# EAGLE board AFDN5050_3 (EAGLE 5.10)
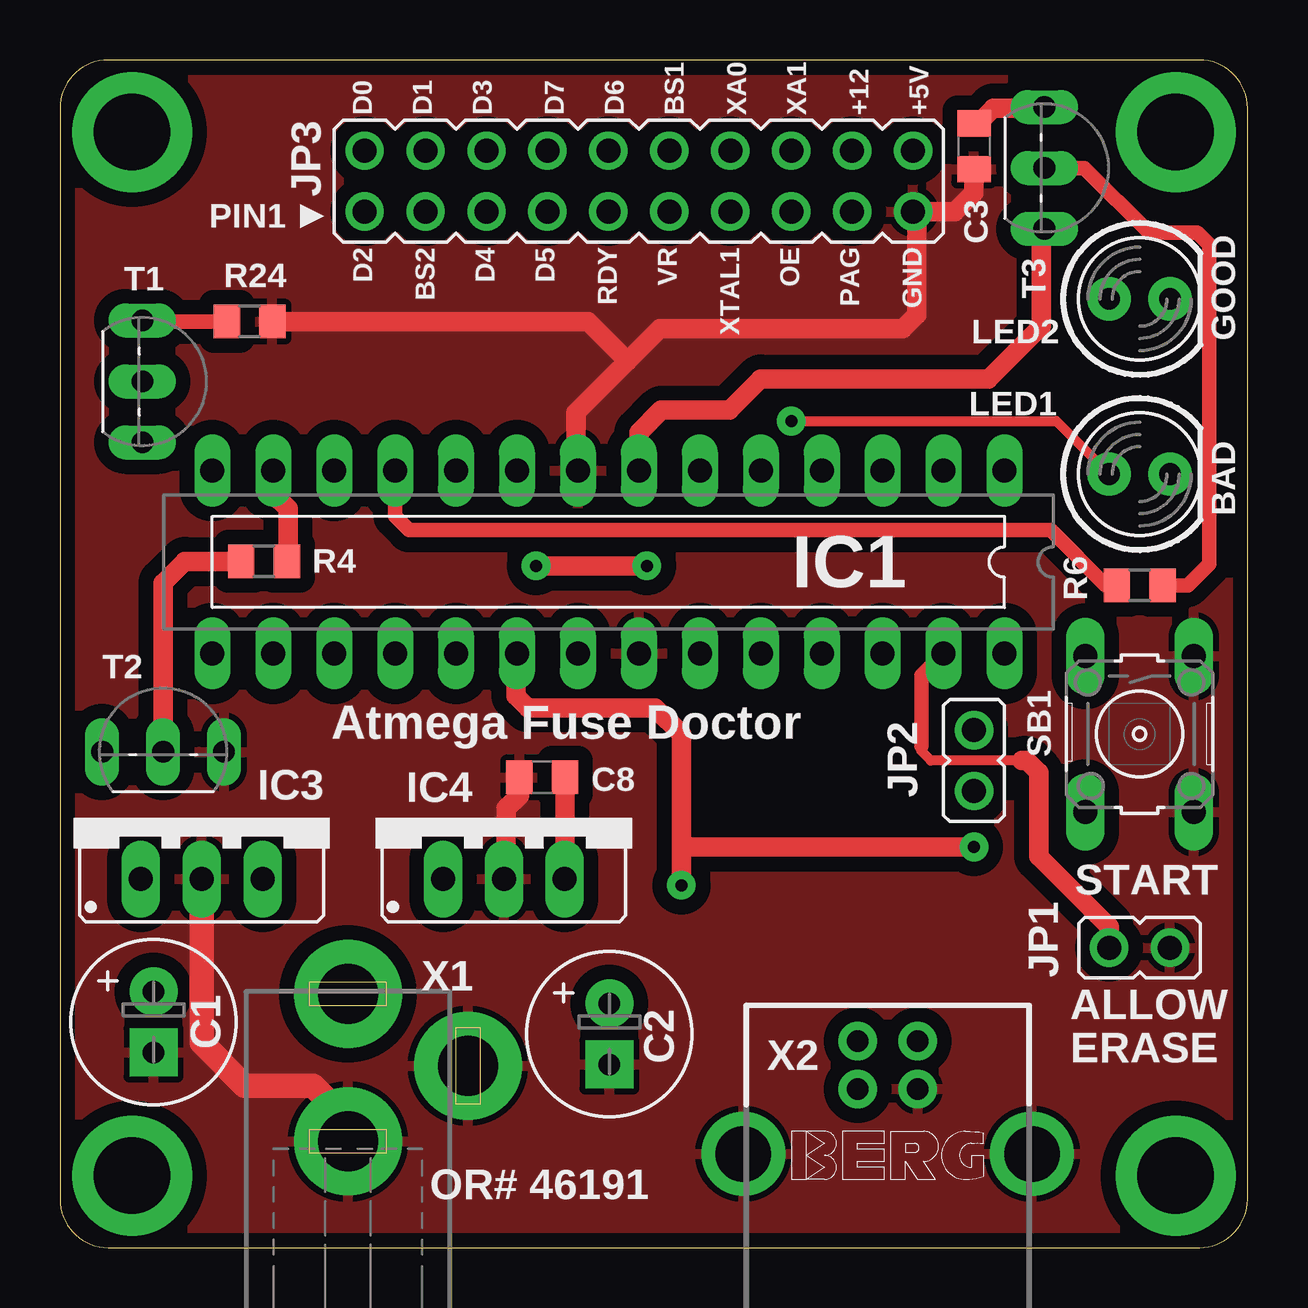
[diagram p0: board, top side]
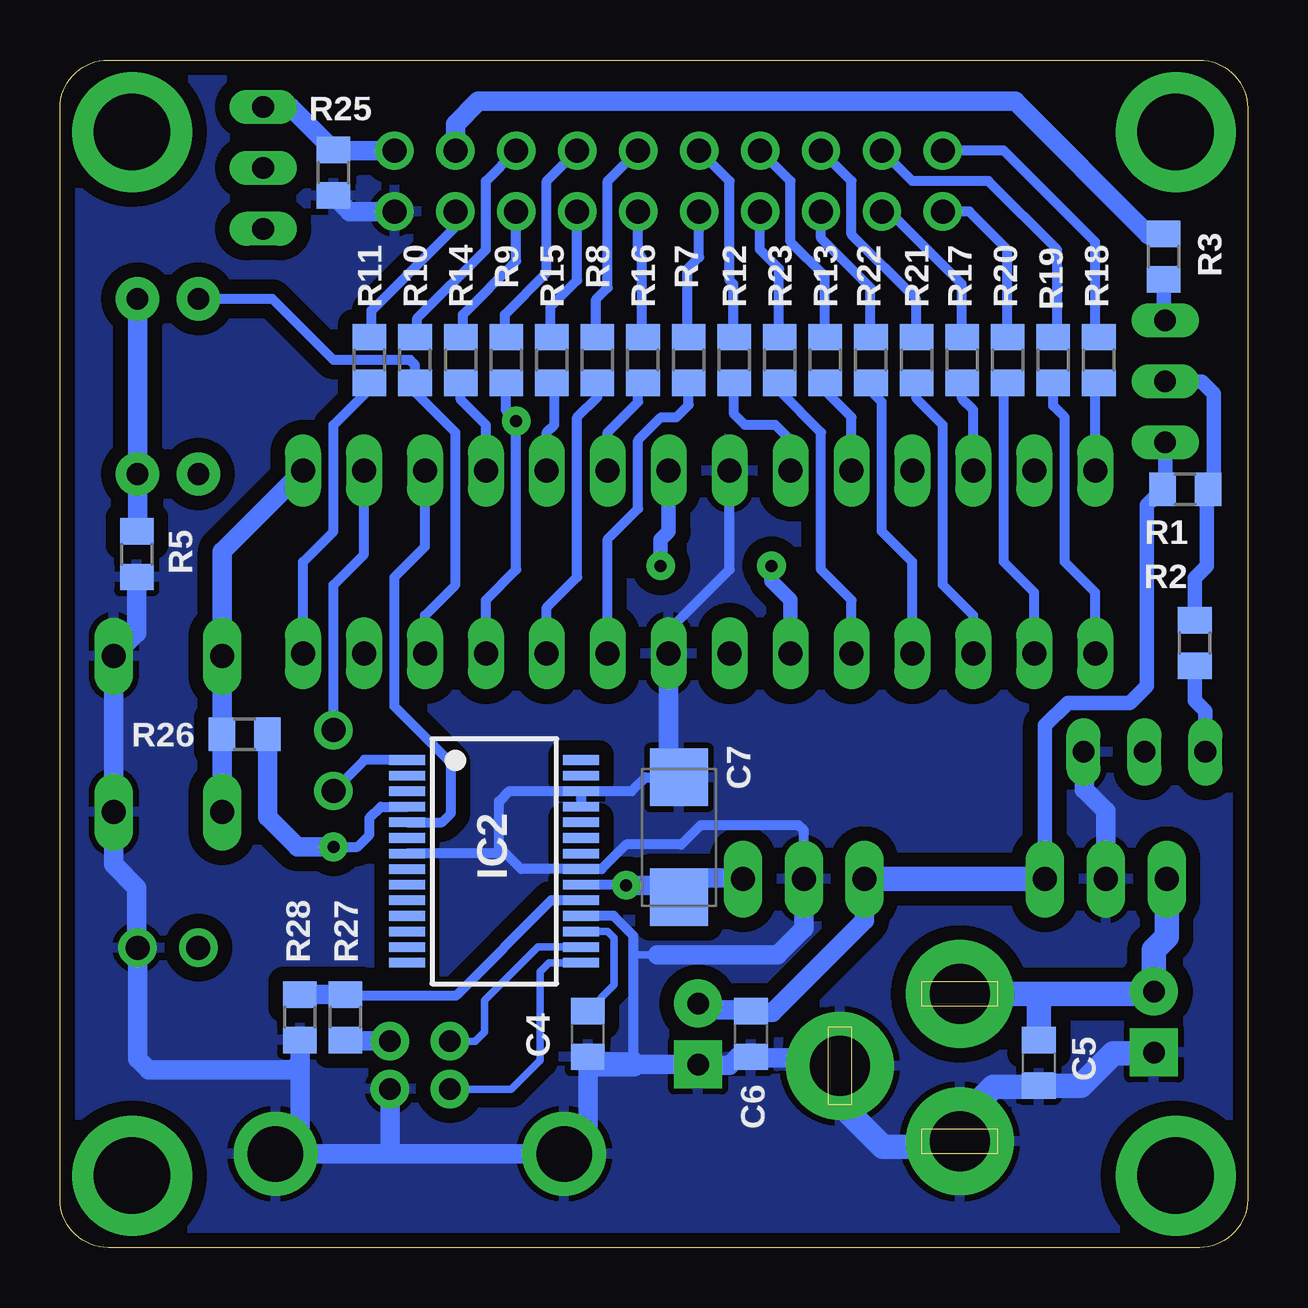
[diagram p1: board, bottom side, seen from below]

Size 49.5 x 49.5 mm. Coordinates in mm from the lower left corner, seen from the top.
Outline: 49.5,47.5 arc90 47.5,49.5 2,49.5 arc90 0,47.5 0,2 arc90 2,0 47.5,0 arc90 49.5,2 49.5,47.5
Copper layers (1*16): Top 0.035mm / dielectric 1.5mm / Bottom 0.035mm
Design rules "Fusion_eagle_rule_v1.1": minimum track width 6mil, minimum drill 12mil, track to track 6mil, track to pad 6mil, pad to pad 6mil, via to via 6mil, smd to smd 0mil, copper to edge 10mil, drill to drill 10mil, minimum pad ring 10mil, minimum via ring 6mil, stop-mask expansion 2mil, vias tented up to drill 100mil, thermal gap 10mil

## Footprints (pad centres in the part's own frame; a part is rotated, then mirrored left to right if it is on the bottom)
E2,5-7 = drill 0.9 pad 2 round: + -1.27,0 | drill 0.9 pad 2 square: - 1.27,0
C0805 = smd 1.1 x 1.4: 1 -0.95,0; 2 0.95,0
SMC_C = smd 2.4 x 2.4: + -2.5,0; - 2.5,0
DIL28-3 = drill 1 pad 1.3 long: 1 -16.51,-3.81; 2 -13.97,-3.81; 3 -11.43,-3.81; 4 -8.89,-3.81; 5 -6.35,-3.81; 6 -3.81,-3.81; 7 -1.27,-3.81; 8 1.27,-3.81; 9 3.81,-3.81; 10 6.35,-3.81; 11 8.89,-3.81; 12 11.43,-3.81; 13 13.97,-3.81; 14 16.51,-3.81; 15 16.51,3.81; 16 13.97,3.81; 17 11.43,3.81; 18 8.89,3.81; 19 6.35,3.81; 20 3.81,3.81; 21 1.27,3.81; 22 -1.27,3.81; 23 -3.81,3.81; 24 -6.35,3.81; 25 -8.89,3.81; 26 -11.43,3.81; 27 -13.97,3.81; 28 -16.51,3.81
SSOP28 = smd 0.4 x 1.5: 1 -4.225,-3.625; 2 -3.575,-3.625; 3 -2.925,-3.625; 4 -2.275,-3.625; 5 -1.625,-3.625; 6 -0.975,-3.625; 7 -0.325,-3.625; 8 0.325,-3.625; 9 0.975,-3.625; 10 1.625,-3.625; 11 2.275,-3.625; 12 2.925,-3.625; 13 3.575,-3.625; 14 4.225,-3.625; 15 4.225,3.625; 16 3.575,3.625; 17 2.925,3.625; 18 2.275,3.625; 19 1.625,3.625; 20 0.975,3.625; 21 0.325,3.625; 22 -0.325,3.625; 23 -0.975,3.625; 24 -1.625,3.625; 25 -2.275,3.625; 26 -2.925,3.625; 27 -3.575,3.625; 28 -4.225,3.625
78XXS = drill 1 pad 1.6 long: GND 0,-2.54; IN -2.54,-2.54; OUT 2.54,-2.54
JP1 = drill 1 pad 1.6 round: 1 0,-1.27; 2 0,1.27
JP10Q = drill 1 pad 1.6 round: 1 -11.43,-1.27; 2 -11.43,1.27; 3 -8.89,-1.27; 4 -8.89,1.27; 5 -6.35,-1.27; 6 -6.35,1.27; 7 -3.81,-1.27; 8 -3.81,1.27; 9 -1.27,-1.27; 10 -1.27,1.27; 11 1.27,-1.27; 12 1.27,1.27; 13 3.81,-1.27; 14 3.81,1.27; 15 6.35,-1.27; 16 6.35,1.27; 17 8.89,-1.27; 18 8.89,1.27; 19 11.43,-1.27; 20 11.43,1.27
LED5MM = drill 0.9 pad 1.8 round: A -1.27,0; K 1.27,0
R0805 = smd 1.1 x 1.4: 1 -0.95,0; 2 0.95,0
B3F-10XX = drill 1 pad 1.6 long: 1 -3.251,2.261; 2 3.251,2.261; 3 -3.251,-2.261; 4 3.251,-2.261
TO92-EBC = drill 0.9 pad 1.3 long: B 0,-1.27; C -2.54,-1.27; E 2.54,-1.27
733980-62 = drill 2.5 pad 4.5 round: 1 0,8.57; 2 0,2.42; 3 5,5.57
PN61729-S = drill 0.9 pad 1.6 round: 1 1.25,4.71; 2 -1.25,4.71; 3 -1.25,2.71; 4 1.25,2.71 | drill 2.3 pad 3.5 round: S1 -6.02,0; S2 6.02,0

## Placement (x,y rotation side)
C1  100m  [E2,5-7]  3.9,9.4 270 top
C2  10m  [E2,5-7]  22.9,8.9 270 top
C3  10n  [C0805]  38.1,45.9 270 top
C4  100n  [C0805]  27.5,8.9 90 bottom
C5  100n  [C0805]  8.7,7.7 270 bottom
C6  100n  [C0805]  20.7,8.9 270 bottom
C7  10m  [SMC_C]  23.7,17.1 90 bottom
C8  100n  [C0805]  20.1,19.6 180 top
IC1  MEGA8-P  [DIL28-3]  22.86,28.57 180 top
IC2  FT232RL  [SSOP28]  31.4,16.1 270 bottom
IC3  7812  [78XXS]  5.9,17.9 0 top
IC4  7805  [78XXS]  18.5,17.9 0 top
JP1  ERASE  [JP1]  45,12.5 90 top
JP2  TXD  [JP1]  38.1,20.3 0 top
JP3  PROG  [JP10Q]  24.13,44.45 0 top
LED1  RED  [LED5MM]  45,32.24 0 top
LED2  GREEN  [LED5MM]  45,39.54 0 top
R1  10K  [R0805]  2.6,31.6 180 bottom
R2  1K  [R0805]  2.2,25.2 90 bottom
R3  100E  [R0805]  3.5,41.3 90 bottom
R4  4K7  [R0805]  8.5,28.6 180 top
R5  330E  [R0805]  46.3,28.9 90 bottom
R6  4K7  [R0805]  45,27.6 0 top
R7  1K  [R0805]  23.3,37 90 bottom
R8  1K  [R0805]  27.1,37 90 bottom
R9  1K  [R0805]  30.9,37 90 bottom
R10  1K  [R0805]  34.7,37 90 bottom
R11  1K  [R0805]  36.6,37 90 bottom
R12  1K  [R0805]  21.4,37 90 bottom
R13  1K  [R0805]  17.6,37 90 bottom
R14  1K  [R0805]  32.8,37 90 bottom
R15  1K  [R0805]  29,37 90 bottom
R16  1K  [R0805]  25.2,37 90 bottom
R17  1K  [R0805]  11.9,37 90 bottom
R18  1K  [R0805]  6.2,37 90 bottom
R19  1K  [R0805]  8.1,37 90 bottom
R20  1K  [R0805]  10,37 90 bottom
R21  1K  [R0805]  13.8,37 90 bottom
R22  1K  [R0805]  15.7,37 90 bottom
R23  1K  [R0805]  19.5,37 90 bottom
R24  1K  [R0805]  7.9,38.6 180 top
R25  100E  [R0805]  38.1,44.8 90 bottom
R26  1K  [R0805]  41.8,21.4 0 bottom
R27  4K7  [R0805]  37.6,9.6 270 bottom
R28  10K  [R0805]  39.5,9.6 90 bottom
SB1  START  [B3F-10XX]  45,21.4 270 top
T1  BC557  [TO92-EBC]  4.7,36.1 270 top
T2  BC547  [TO92-EBC]  4.3,21.93 0 top
T3  BC557  [TO92-EBC]  42.3,45 270 top
X1  +12-15v  [733980-62]  12,2 0 top
X2  PN61729-S  [PN61729-S]  34.5,3.9 0 top

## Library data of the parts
C1 C2 IC1 IC3 IC4 JP1-JP3 LED1 LED2 SB1 T1-T3 X1 X2 = AFDN
C3-C8 R1-R28 = rcl
IC2 = ftdichip

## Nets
+5V: C3.1 JP3.20 R25.2 T3.C
+12V: JP3.18 R3.2
BS1: JP3.12 R8.2
BS2: JP3.3 R17.2
DATA0: JP3.2 R18.2
DATA1: JP3.4 R19.2
DATA2: JP3.1 R20.2
DATA3: JP3.6 R21.2
DATA4: JP3.5 R22.2
DATA5: JP3.7 R23.2
DATA6: JP3.10 R12.2
DATA7: JP3.8 R13.2
GND: C1.- C2.- C3.2 C4.1 C5.2 C6.2 C7.- C8.2 IC1.8 IC1.22 IC2.7 IC2.18 IC2.21 IC2.25 IC2.26 IC3.GND IC4.GND JP1.1 JP3.19 R5.1 R24.1 R25.1 R28.1 SB1.1 SB1.2 T2.E X1.2 X1.3 X2.4 X2.S1 X2.S2
N$1: IC1.1 R26.1 SB1.3 SB1.4
N$2: IC1.28 R11.1
N$3: IC1.2 JP2.2
N$4: IC2.1 JP2.1
N$5: IC1.26 LED2.A R10.1
N$6: IC1.25 LED1.A R9.1
N$7: IC1.24 R8.1
N$8: IC1.23 R7.1
N$9: IC1.4 R14.1
N$10: IC1.5 R15.1
N$11: IC1.6 R16.1
N$12: IC1.12 R17.1
N$13: IC1.14 R18.1
N$14: IC1.15 R19.1
N$15: IC1.16 R20.1
N$16: IC1.17 R21.1
N$17: IC1.18 R22.1
N$18: IC1.19 R23.1
N$19: IC1.9 R12.1
N$20: IC1.10 R13.1
N$21: LED1.K LED2.K R5.2
N$22: IC1.27 JP1.2
N$23: IC1.11 R6.1
N$24: IC1.13 R4.1
N$25: R6.2 T3.B
N$26: R4.2 T2.B
N$27: C1.+ C5.1 IC3.IN X1.1
N$28: R2.1 T2.C
N$29: R3.1 R24.2 T1.C
N$30: R1.1 R2.2 T1.B
N$31: IC2.16 X2.2
N$32: IC2.15 X2.3
N$34: R27.2 X2.1
N$35: IC2.19 R27.1 R28.2
N$36: C4.2 IC2.17
OE: JP3.15 R14.2
PAG: JP3.17 R11.2
RDY: JP3.9 R7.2
RXD: IC1.3 IC2.5
V+: C2.+ C6.1 IC3.OUT IC4.IN R1.2 T1.E
VCC: C7.+ C8.1 IC1.7 IC1.20 IC2.4 IC2.20 IC4.OUT R26.2 T3.E
WR: JP3.11 R16.2
XA0: JP3.14 R9.2
XA1: JP3.16 R10.2
XTAL1: JP3.13 R15.2

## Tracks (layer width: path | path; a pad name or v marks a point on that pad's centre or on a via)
+5V
  Top 0.813: C3.1 38.25,46.85 38.9,47.5 40.99,47.5 T3.C
  Bottom 0.813: T3.C 39.89,47.54 R25.2 | R25.2 38.08,45.77 | JP3.20 38.07,45.72 R25.2
+12V
  Bottom 0.813: JP3.18 33.02,46.83 32.07,47.78 9.68,47.78 4.13,42.23 3.52,42.23 R3.2
BS1
  Bottom 0.406: JP3.12 26.67,44.45 26.67,40.01 27.15,39.53 27.15,38 R8.2
BS2
  Bottom 0.406: JP3.3 14.92,43.18 11.91,40.16 R17.2
DATA0
  Bottom 0.406: JP3.2 10.16,45.72 6.35,41.91 6.35,38.1 R18.2
DATA1
  Bottom 0.406: JP3.4 13.97,44.45 10.79,44.45 7.94,41.59 7.94,38.11 R19.2
DATA2
  Bottom 0.406: JP3.1 11.59,43.18 10,41.59 R20.2
DATA3
  Bottom 0.406: JP3.6 16.51,44.45 16.51,42.23 13.81,39.53 R21.2
DATA4
  Bottom 0.406: JP3.5 17.78,42.07 15.72,40.01 15.72,37.97 R22.2
DATA5
  Bottom 0.406: JP3.7 20.32,41.59 19.53,40.8 19.53,37.98 R23.2
DATA6
  Bottom 0.406: JP3.10 21.59,44.45 21.59,40.32 21.43,40.16 21.43,37.98 R12.2
DATA7
  Bottom 0.406: JP3.8 19.05,44.45 19.05,41.91 17.62,40.48 17.62,37.97 R13.2
GND
  Top 0.813: 23.65,36.95 21.5,34.8 21.5,32.33 IC1.8 | 23.65,36.95 25,38.3 35.12,38.3 35.72,38.89 35.72,43.02 JP3.19 37.31,43.18 38.1,43.97 C3.2 | R24.1 22,38.6 23.65,36.95 | C8.2 19.15,18.85 18.6,18.3 18.6,15.46 IC4.GND
  Top 1.016: IC3.GND 5.9,8.55 7.7,6.75 10.55,6.75 11.9,5.4 11.9,4.52 X1.2
  Bottom 0.305: C4.1 27.45,8 | 25.6,12.2 24.6,12.2 | IC1.22 24.12,24.75
  Bottom 0.406: IC2.26 30.77,19.02 31.2,18.6 31.2,16.43 | IC2.26 IC2.25 | 31.2,16.43 30.93,16.43 30.27,15.78 IC2.21 26.93,15.78 25.9,16.8 23.6,16.8 22.8,17.6 18.7,17.6 18.5,17.4 IC4.GND | 31.2,16.43 IC2.7 | IC2.18 26.43,13.82 25.6,13 25.6,12.2 25.6,7.63 | IC1.8 21.59,28.26 24.13,25.72 IC1.22 | IC2.26 25.68,19.02 25.1,19.6 C7.-
  Bottom 0.813: R5.1 46.3,25.61 SB1.1 SB1.2 47.26,15.96 46.3,15 46.3,12.53 JP1.1 46.27,7.87 45.8,7.4 39.8,7.4 39.5,7.7 | 35.8,3.9 X2.S1 27.5,4.88 C4.1 | 35.8,3.9 39.6,3.9 | 39.6,3.9 X2.S2 | X2.4 35.75,3.95 35.8,3.9 | 39.5,7.7 39.5,4 39.6,3.9 | 39.5,7.7 R28.1 | IC3.GND 5.9,18.2 6.8,19.1 6.8,20.62 T2.E | IC4.GND 18.5,13.3 19.6,12.2 24.6,12.2 | JP3.19 37.43,43.18 R25.1 | 25.6,7.63 C2.- 22.87,7.6 21.6,7.6 21.25,7.95 C6.2 20.65,7.9 17.4,7.9 17.07,7.57 X1.3 | IC1.22 24.13,20.03 C7.-
  Bottom 1.016: X1.3 17,6 15.2,4.2 12.22,4.2 X1.2 12,5.3 10.6,6.7 8.75,6.7 C5.2 6.95,6.75 5.6,8.1 3.93,8.1 C1.- | 25.6,7.63 27.18,7.63 C4.1
  pour Bottom (isolate 0.61): 7,49.5 2,49.5 arc90 0,47.5 0,47 0,2 arc90 2,0 47.5,0 arc90 49.5,2 49.5,6.5 49.5,47.5 arc90 47.5,49.5
  pour Top (isolate 0.61): 0,16 0,2 arc90 2,0 3,0 47.5,0 arc90 49.5,2 49.5,4 49.5,47.5 arc90 47.5,49.5 45,49.5 2,49.5 arc90 0,47.5 0,46
N$1
  Bottom 0.813: SB1.4 42.74,21.39 R26.1 SB1.3 42.74,29.02 IC1.1
N$2
  Bottom 0.406: R11.1 36.6,35.79 38.1,34.29 38.1,29.84 39.37,28.57 IC1.28
N$3
  Bottom 0.406: IC1.2 36.83,28.89 38.1,27.62 JP2.2
N$4
  Bottom 0.406: IC2.1 36.8,20.32 JP2.1
N$5
  Bottom 0.406: LED2.A 40.64,39.54 38.1,37 34.9,37 34.7,36.8 R10.1 34.7,35.65 33.02,33.97 33.02,27.62 34.29,26.35 IC1.26
N$6  (via drill 0.5 pad 1.2)
  Top 0.406: v30.48,34.45 41.52,34.45 LED1.A
  Bottom 0.406: R9.1 30.9,34.87 v30.48,34.45 30.48,28.26 31.75,26.99 IC1.25
N$7
  Bottom 0.406: R8.1 27.1,35.45 27.94,34.61 27.94,27.94 29.21,26.67 IC1.24
N$8
  Bottom 0.406: R7.1 23.3,35.12 23.81,34.61 24.45,34.61 25.4,33.66 25.4,30.8 26.67,29.53 IC1.23
N$9
  Bottom 0.406: R14.1 32.8,35.34 31.75,34.29 IC1.4
N$10
  Bottom 0.406: R15.1 29.1,35.95 29.1,35.77 28.89,35.56 28.89,34.29 29.21,33.97 IC1.5
N$11
  Bottom 0.406: IC1.6 26.67,33.97 25.4,35.24 25.4,35.85 R16.1
N$12
  Bottom 0.406: R17.1 11.9,35.4 11.43,34.92 IC1.12
N$13
  Bottom 0.406: IC1.14 6.35,35.9 R18.1
N$14
  Bottom 0.406: R19.1 8.1,35.09 7.62,34.61 7.62,28.57 6.35,27.3 IC1.15
N$15
  Bottom 0.406: R20.1 10,35.72 10.16,35.56 10.16,28.57 8.89,27.3 IC1.16
N$16
  Bottom 0.406: R21.1 13.8,35.39 12.7,34.29 12.7,27.62 11.43,26.35 IC1.17
N$17
  Bottom 0.406: R22.1 15.7,35.7 15.24,35.24 15.24,29.84 13.97,28.57 IC1.18
N$18
  Bottom 0.406: R23.1 19.5,35.69 17.78,33.97 17.78,28.26 16.51,26.99 IC1.19
N$19
  Bottom 0.406: R12.1 21.4,34.73 20.95,34.29 19.68,34.29 19.05,33.66 IC1.9
N$20
  Bottom 0.406: R13.1 17.6,35.7 16.51,34.61 IC1.10
N$21
  Bottom 0.813: LED2.K LED1.K 46.27,29.88 R5.2
N$22
  Top 0.406: 40.1,20.3 36.3,20.3 35.9,20.7 35.9,20.9
  Top 0.61: 35.9,20.9 35.9,23.84 IC1.27
  Top 0.813: JP1.2 43.73,13.37 40.8,16.3 40.8,19.8 40.3,20.3 40.1,20.3
N$23
  Top 0.61: R6.1 43.6,27.6 41.3,29.9 14.55,29.9 13.97,30.48 IC1.11
N$24
  Top 0.813: IC1.13 8.89,31.41 9.5,30.8 9.5,28.65 R4.1
N$25
  Top 0.61: R6.2 47,27.6 47.9,28.5 47.9,41.8 47.4,42.3 45.4,42.3 42.7,45 T3.B
N$26
  Top 0.813: T2.B 4.3,27.7 5.2,28.6 R4.2
N$27
  Bottom 1.016: 8.6,10.57 X1.1 | C5.1 8.7,10.47 8.6,10.57 | 8.6,10.57 4.14,10.57 arc-45 C1.+ 3.9,12.4 3.36,12.94 IC3.IN
N$28
  Bottom 0.61: T2.C 1.76,22.36 2.2,22.8 R2.1
N$29
  Top 0.61: R24.2 3.47,38.6 T1.C
  Bottom 0.61: R3.1 3.5,38.71 T1.C
N$30
  Bottom 0.61: T1.B 1.9,36.1 1.4,35.6 1.4,31.85 R1.1 1.7,31.55 1.7,28.4 2.2,27.9 R2.2
N$31
  Bottom 0.305: IC2.16 29.57,12.53 31.8,10.3 31.8,9 32.2,8.6 X2.2
N$32
  Bottom 0.305: IC2.15 29.12,11.88 29.5,11.5 29.5,7.8 30.7,6.6 X2.3
N$33  (via drill 3.2 pad 5)
  other vias: 3,3
N$34
  Bottom 0.813: X2.1 37.56,8.61 R27.2
N$35
  Bottom 0.305: 37.55,10.5 R27.1
  Bottom 0.406: IC2.19 29.02,14.47 33,10.5 37.55,10.5
  Bottom 0.813: R27.1 R28.2
N$36
  Bottom 0.305: IC2.17 26.68,13.18 26.4,12.9 26.4,10.95 C4.2
N$37  (via drill 3.2 pad 5)
  other vias: 46.5,3
N$38  (via drill 3.2 pad 5)
  other vias: 46.5,46.5
N$39  (via drill 3.2 pad 5)
  other vias: 3,46.5
OE
  Bottom 0.406: JP3.15 30.48,41.12 32.7,38.89 32.7,38.05 R14.2
PAG
  Bottom 0.406: JP3.17 33.02,42.55 36.51,39.05 36.51,38.04 R11.2
RDY
  Bottom 0.406: JP3.9 22.86,41.27 23.34,40.8 23.34,37.99 R7.2
RXD
  Bottom 0.406: IC2.5 33.58,17.73 33.2,18.1 33.2,20.2 35.56,22.56 35.56,23.5 35.56,27.94 34.29,29.21 IC1.3
V+
  Bottom 0.61: IC3.OUT 8.44,21.76 7.5,22.7 4.9,22.7 4.2,23.4 4.2,30.95 R1.2 3.43,31.72 T1.E
  Bottom 0.813: C2.+ 22.9,10.1 22.7,9.9 20.75,9.9 C6.1 20.65,9.8 19.8,9.8 15.96,13.64 IC4.IN
  Bottom 1.016: IC3.OUT IC4.IN
VCC  (via drill 0.5 pad 1.2)
  Top 0.813: v19.84,28.42 v24.46,28.42 | v25.9,15.1 25.9,16.7 | 25.9,16.7 25.9,21.4 24.8,22.5 19.5,22.5 19,23 19,24.71 IC1.20 | 25.9,16.7 v38.1,16.7 | T3.E 40.9,42.33 40.9,38.4 38.7,36.2 29.2,36.2 27.9,34.9 25.06,34.9 24.13,33.97 IC1.7 | C8.1 IC4.OUT
  Bottom 0.305: v25.9,15.1 25.93,15.12
  Bottom 0.406: 25.93,15.12 IC2.20 | IC2.4 36.12,18.38 36.6,17.9 36.6,17.2 37.1,16.7 v38.1,16.7
  Bottom 0.61: v19.84,28.42 19.84,27.78 19.05,26.99 IC1.20 | v24.46,28.42 24.46,29.52 24.13,29.84 IC1.7
  Bottom 0.813: R26.2 40.85,17.95 39.6,16.7 v38.1,16.7 | v25.9,15.1 24.2,15.1 C7.+ 22.9,15.4 21.08,15.4 IC4.OUT
WR
  Bottom 0.406: JP3.11 25.4,41.43 25.24,41.27 25.24,37.99 R16.2
XA0
  Bottom 0.406: JP3.14 29.21,44.45 29.21,40.64 30.96,38.89 30.96,38.01 R9.2
XA1
  Bottom 0.406: JP3.16 31.75,44.45 31.75,41.59 34.61,38.73 34.61,38.04 R10.2
XTAL1
  Bottom 0.406: JP3.13 27.94,40.32 29.05,39.21 29.05,38 R15.2

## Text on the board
tPlace: D0 | D1 | D3 | D7 | D6 | BS1 | XA0 | XA1 | +12 | +5V | PIN1 | D2 | BS2 | D4 | D5 | RDY | VR | XTAL1 | OE | PAG | GND | GOOD | BAD | Atmega Fuse Doctor | START | ALLOW | ERASE | OR# 46191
